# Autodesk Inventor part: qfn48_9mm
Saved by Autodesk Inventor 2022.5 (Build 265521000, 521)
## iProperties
Created: 2024-12
Part Number: qfn48_9mm
Material: Generic
Document SubType Name: Modeling
Designer: AdminForWorker
Density: 1 g/cm^3
Appearance: Default
Title: qfn48_9mm v1
Author: AdminForWorker
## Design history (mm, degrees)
feature "Body1"
feature "Body64"
feature "Body65"
feature "Body66"
feature "Body67"
feature "Body68"
feature "Body69"
feature "Body70"
feature "Body71"
feature "Body72"
feature "Body73"
feature "Body74"
feature "Body75"
feature "Body103"
feature "Body104"
feature "Body105"
feature "Body85"
feature "Body86"
feature "Body87"
feature "Body88"
feature "Body89"
feature "Body90"
feature "Body109"
feature "Body110"
feature "Body111"
feature "Body106"
feature "Body107"
feature "Body108"
feature "Body91"
feature "Body92"
feature "Body93"
feature "Body94"
feature "Body95"
feature "Body96"
feature "Body100"
feature "Body101"
feature "Body102"
feature "Body76"
feature "Body77"
feature "Body78"
feature "Body97"
feature "Body98"
feature "Body99"
feature "Body82"
feature "Body83"
feature "Body84"
feature "Body79"
feature "Body80"
feature "Body81"
body "Solid1"
body "Solid2"
body "Solid3"
body "Solid4"
body "Solid5"
body "Solid6"
body "Solid7"
body "Solid8"
body "Solid9"
body "Solid10"
body "Solid11"
body "Solid12"
body "Solid13"
body "Solid14"
body "Solid15"
body "Solid16"
body "Solid17"
body "Solid18"
body "Solid19"
body "Solid20"
body "Solid21"
body "Solid22"
body "Solid23"
body "Solid24"
body "Solid25"
body "Solid26"
body "Solid27"
body "Solid28"
body "Solid29"
body "Solid30"
body "Solid31"
body "Solid32"
body "Solid33"
body "Solid34"
body "Solid35"
body "Solid36"
body "Solid37"
body "Solid38"
body "Solid39"
body "Solid40"
body "Solid41"
body "Solid42"
body "Solid43"
body "Solid44"
body "Solid45"
body "Solid46"
body "Solid47"
body "Solid48"
body "Solid49"
